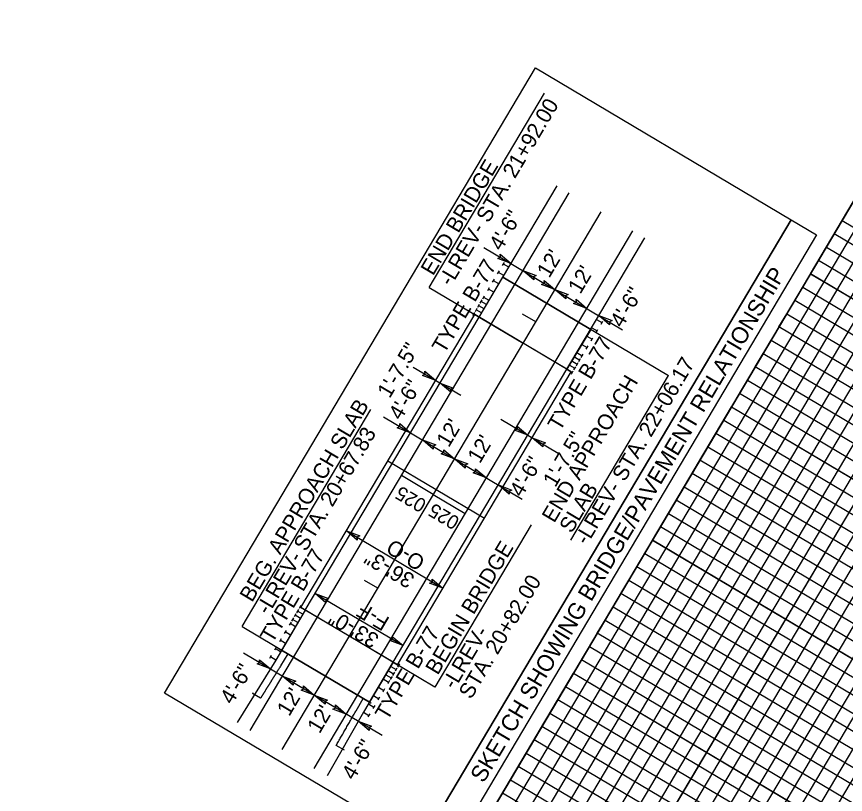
# Model space of a CAD drawing. Extents: x 2137081 to 2142019, y 404041 to 411238.
# Drawn here: x 2140819.3 to 2141087, y 409749.2 to 410000.3 of the extents above; entities that cross this region are included whole.
import ezdxf

# ---------------------------------------------------------------- set-up
doc = ezdxf.new("R2010")
doc.units = 0
for name, color, linetype in [('Prop Approach Slab', 7, 'Continuous'), ('Prop Approach Slab Hatching', 7, 'Continuous'), ('Prop Dimension', 7, 'Continuous'), ('Prop Dimension Text', 7, 'Continuous'), ('Prop EOT', 7, 'Continuous'), ('Prop Horizontal Alignment', 7, 'Continuous'), ('Prop Horizontal Alignment Tick Small', 7, 'Continuous'), ('Prop Roadway Bridge', 7, 'Continuous'), ('Prop SBG', 7, 'Continuous'), ('Prop Structure Anchor Unit CELL', 7, 'Continuous'), ('Prop Superelevation  Arrow CELL', 7, 'Continuous'), ('Prop Terminator CELL', 7, 'Continuous'), ('Sheet Clip Boundary CELL', 7, 'Continuous'), ('Sheet DOT Grid CELL', 7, 'Continuous'), ('Sheet Layout Profile Border Port 2', 7, 'Continuous'), ('Sheet Profile Grid Major CELL', 7, 'Continuous'), ('Sheet Profile Grid Middle CELL', 7, 'Continuous'), ('Sheet Profile Grid Minor CELL', 7, 'Continuous')]:
    doc.layers.add(name, color=color, linetype=linetype)

msp = doc.modelspace()

# ---------------------------------------------------------------- linework, layer by layer
at = {"layer": 'Prop Approach Slab'}
for p, q in [((2140968.66, 409903.27), (2140976.32, 409916.17)), ((2141004.7, 409899.32), (2140976.32, 409916.17)), ((2140912.52, 409808.67), (2140904.86, 409795.77)), ((2140933.24, 409778.93), (2140904.86, 409795.77))]:
    msp.add_line(p, q, dxfattribs=at)
at = {"layer": 'Prop Approach Slab Hatching'}
for points in [[(2140968.66, 409903.27), (2140976.32, 409916.17), (2141004.7, 409899.32), (2140997.04, 409886.42)], [(2140933.24, 409778.93), (2140940.9, 409791.83), (2140912.52, 409808.67), (2140904.86, 409795.77)]]:
    msp.add_lwpolyline(points, close=True, dxfattribs=at)
at = {"layer": 'Prop Dimension'}
for p, q in [((2140970.23, 409925.79), (2141015.01, 409899.21)), ((2140952.51, 409912.85), (2140982.85, 409894.84)), ((2140990.51, 409907.74), (2141029.85, 409884.39)), ((2140947.31, 409887.17), (2140962.72, 409878.03)), ((2140937.77, 409871.1), (2140982.55, 409844.52)), ((2140975.64, 409870.36), (2140994.15, 409859.38)), ((2140925.81, 409834.25), (2140956.98, 409815.75)), ((2140915.71, 409814.05), (2140944.09, 409797.21)), ((2140892.1, 409803.35), (2140919.05, 409787.35)), ((2140892.52, 409794.86), (2140937.3, 409768.28)), ((2140954.34, 409783.85), (2140934.08, 409795.87))]:
    msp.add_line(p, q, dxfattribs=at)
at = {"layer": 'Prop Dimension Text'}
for p, q in [((2140952.51, 409912.85), (2140989.73, 409975.56)), ((2140998.33, 409831.28), (2141029.85, 409884.39)), ((2140892.1, 409803.35), (2140933.67, 409873.4)), ((2140985.42, 409836.22), (2140954.34, 409783.85))]:
    msp.add_line(p, q, dxfattribs=at)
for points in [[(2141069.43, 409934.69), (2140949.64, 409732.86), (2140867.04, 409781.89), (2140986.83, 409983.72)], [(2140949.64, 409732.86), (2141069.43, 409934.69), (2141077.67, 409929.8), (2140957.88, 409727.97)]]:
    msp.add_lwpolyline(points, close=True, dxfattribs=at)
at = {"layer": 'Prop EOT'}
for p, q in [((2140978.23, 409919.39), (2140993.85, 409945.69)), ((2140894.69, 409769.82), (2140997.72, 409943.4)), ((2140915.33, 409757.57), (2141018.35, 409931.15)), ((2141006.61, 409902.55), (2141022.22, 409928.85)), ((2140902.95, 409792.55), (2140890.49, 409772.43)), ((2140931.33, 409775.71), (2140919.53, 409755.16))]:
    msp.add_line(p, q, dxfattribs=at)
at = {"layer": 'Prop Horizontal Alignment'}
msp.add_line((2140905.01, 409763.7), (2141008.03, 409937.27), dxfattribs=at)
at = {"layer": 'Prop Horizontal Alignment Tick Small'}
for p, q in [((2140986.94, 409901.72), (2140982.64, 409904.28)), ((2140935.89, 409815.73), (2140931.6, 409818.28))]:
    msp.add_line(p, q, dxfattribs=at)
at = {"layer": 'Prop Roadway Bridge'}
for p, q in [((2140911.12, 409809.5), (2140967.27, 409904.1)), ((2140998.44, 409885.59), (2140967.27, 409904.1)), ((2140912.52, 409808.67), (2140968.66, 409903.27)), ((2140940.9, 409791.83), (2140997.04, 409886.42)), ((2140942.29, 409791), (2140998.44, 409885.59)), ((2140970.37, 409838.3), (2140939.19, 409856.8)), ((2140942.29, 409791), (2140911.12, 409809.5))]:
    msp.add_line(p, q, dxfattribs=at)
at = {"layer": 'Prop SBG'}
for p, q in [((2140904.26, 409796.13), (2140904.86, 409795.77)), ((2140906.87, 409794.58), (2140904.53, 409790.65)), ((2140895.6, 409782.01), (2140895.47, 409781.78)), ((2140898.07, 409780.24), (2140895.47, 409781.78)), ((2140896.19, 409781.64), (2140896.06, 409781.43)), ((2140928.9, 409776.18), (2140931.24, 409780.12)), ((2140933.84, 409778.57), (2140933.24, 409778.93)), ((2140925.13, 409763.51), (2140922.5, 409765.02))]:
    msp.add_line(p, q, dxfattribs=at)
msp.add_open_spline([(2140904.5, 409790.61), (2140904.23, 409790.16), (2140903.95, 409789.71), (2140903.67, 409789.27), (2140903.53, 409789.04), (2140903.4, 409788.82), (2140903.26, 409788.6), (2140903.12, 409788.37), (2140902.98, 409788.15), (2140902.84, 409787.93), (2140902.7, 409787.7), (2140902.56, 409787.48), (2140902.42, 409787.26), (2140902.29, 409787.03), (2140902.15, 409786.81), (2140902.01, 409786.59), (2140901.87, 409786.36), (2140901.73, 409786.14), (2140901.59, 409785.92), (2140901.45, 409785.69), (2140901.32, 409785.47), (2140901.18, 409785.25), (2140901.04, 409785.02), (2140900.9, 409784.8), (2140900.76, 409784.58), (2140900.62, 409784.35), (2140900.48, 409784.13), (2140900.35, 409783.91), (2140900.21, 409783.69), (2140900.07, 409783.46), (2140899.93, 409783.24), (2140899.79, 409783.02), (2140899.65, 409782.79), (2140899.51, 409782.57), (2140899.37, 409782.35), (2140899.24, 409782.12), (2140899.1, 409781.9), (2140898.96, 409781.68), (2140898.82, 409781.45), (2140898.68, 409781.23), (2140898.54, 409781.01), (2140898.4, 409780.78), (2140898.27, 409780.56), (2140898.2, 409780.45), (2140898.13, 409780.34), (2140898.07, 409780.24)], degree=3, dxfattribs=at)
msp.add_spline([(2140922.5, 409765.02), (2140922.66, 409765.31), (2140923.05, 409765.98), (2140923.44, 409766.66), (2140923.83, 409767.34), (2140924.22, 409768.02), (2140924.61, 409768.69), (2140925, 409769.37), (2140925.38, 409770.05), (2140925.77, 409770.73), (2140926.16, 409771.41), (2140926.55, 409772.08), (2140926.94, 409772.76), (2140927.33, 409773.44), (2140927.72, 409774.12), (2140928.1, 409774.8), (2140928.88, 409776.15)], degree=3, dxfattribs=at)
at = {"layer": 'Prop Structure Anchor Unit CELL'}
for p, q in [((2140976.22, 409919.92), (2140976.81, 409920.9)), ((2140978.23, 409919.39), (2140976.51, 409920.41)), ((2140968.66, 409903.27), (2140978.23, 409919.39)), ((2140974.63, 409917.23), (2140975.21, 409918.22)), ((2140976.64, 409916.7), (2140974.92, 409917.72)), ((2140973.03, 409914.54), (2140973.62, 409915.53)), ((2140975.04, 409914.02), (2140973.32, 409915.04)), ((2140971.44, 409911.86), (2140972.02, 409912.84)), ((2140973.45, 409911.33), (2140971.73, 409912.35)), ((2140969.84, 409909.17), (2140970.43, 409910.15)), ((2140971.85, 409908.64), (2140970.13, 409909.66)), ((2140968.25, 409906.48), (2140968.83, 409907.47)), ((2140970.26, 409905.95), (2140968.54, 409906.97)), ((2140969.04, 409907.83), (2140969.63, 409908.81)), ((2140971.06, 409907.3), (2140969.34, 409908.32)), ((2140966.65, 409903.79), (2140967.24, 409904.78)), ((2140968.66, 409903.27), (2140966.94, 409904.29)), ((2140967.45, 409905.14), (2140968.03, 409906.12)), ((2140969.46, 409904.61), (2140967.74, 409905.63)), ((2140997.04, 409886.42), (2141006.61, 409902.55)), ((2141006.61, 409902.55), (2141008.33, 409901.53)), ((2141008.04, 409901.03), (2141008.62, 409902.02)), ((2141005.02, 409899.86), (2141006.74, 409898.84)), ((2141006.44, 409898.35), (2141007.03, 409899.33)), ((2141003.42, 409897.17), (2141005.14, 409896.15)), ((2141004.85, 409895.66), (2141005.43, 409896.64)), ((2141001.83, 409894.48), (2141003.55, 409893.46)), ((2141003.25, 409892.97), (2141003.84, 409893.96)), ((2140999.43, 409890.45), (2141001.15, 409889.43)), ((2141000.23, 409891.8), (2141001.95, 409890.78)), ((2141001.66, 409890.28), (2141002.24, 409891.27)), ((2140997.84, 409887.77), (2140999.56, 409886.75)), ((2140998.64, 409889.11), (2141000.36, 409888.09)), ((2141000.06, 409887.6), (2141000.65, 409888.58)), ((2141000.86, 409888.94), (2141001.45, 409889.93)), ((2140997.04, 409886.42), (2140998.76, 409885.4)), ((2140998.47, 409884.91), (2140999.05, 409885.89)), ((2140999.27, 409886.25), (2140999.85, 409887.24)), ((2140911.09, 409810.19), (2140910.51, 409809.2)), ((2140912.52, 409808.67), (2140902.95, 409792.55)), ((2140909.5, 409807.5), (2140908.91, 409806.51)), ((2140910.29, 409808.84), (2140909.71, 409807.86)), ((2140911.72, 409807.33), (2140910, 409808.35)), ((2140912.52, 409808.67), (2140910.8, 409809.69)), ((2140907.9, 409804.81), (2140907.32, 409803.83)), ((2140908.7, 409806.16), (2140908.11, 409805.17)), ((2140910.13, 409804.64), (2140908.41, 409805.66)), ((2140910.92, 409805.99), (2140909.2, 409807.01)), ((2140906.31, 409802.12), (2140905.72, 409801.14)), ((2140909.33, 409803.3), (2140907.61, 409804.32)), ((2140904.71, 409799.44), (2140904.13, 409798.45)), ((2140907.73, 409800.61), (2140906.01, 409801.63)), ((2140903.12, 409796.75), (2140902.53, 409795.77)), ((2140906.14, 409797.92), (2140904.42, 409798.94)), ((2140901.52, 409794.06), (2140900.94, 409793.08)), ((2140904.54, 409795.24), (2140902.82, 409796.26)), ((2140902.95, 409792.55), (2140901.23, 409793.57)), ((2140940.9, 409791.83), (2140931.33, 409775.71)), ((2140940.9, 409791.83), (2140942.62, 409790.81)), ((2140939.3, 409789.14), (2140941.02, 409788.12)), ((2140940.1, 409790.49), (2140941.82, 409789.47)), ((2140942.11, 409789.96), (2140941.53, 409788.97)), ((2140942.91, 409791.3), (2140942.32, 409790.32)), ((2140937.71, 409786.46), (2140939.43, 409785.43)), ((2140938.5, 409787.8), (2140940.22, 409786.78)), ((2140940.52, 409787.27), (2140939.93, 409786.29)), ((2140941.31, 409788.61), (2140940.73, 409787.63)), ((2140936.11, 409783.77), (2140937.83, 409782.75)), ((2140939.72, 409785.93), (2140939.13, 409784.94)), ((2140934.52, 409781.08), (2140936.24, 409780.06)), ((2140938.12, 409783.24), (2140937.54, 409782.25)), ((2140932.92, 409778.39), (2140934.64, 409777.37)), ((2140936.53, 409780.55), (2140935.94, 409779.57)), ((2140931.33, 409775.71), (2140933.05, 409774.69)), ((2140934.93, 409777.87), (2140934.35, 409776.88)), ((2140933.34, 409775.18), (2140932.75, 409774.19))]:
    msp.add_line(p, q, dxfattribs=at)
at = {"layer": 'Prop Superelevation  Arrow CELL'}
for q in [(2140943.54, 409852.13), (2140964.18, 409839.88)]:
    msp.add_line((2140953.86, 409846), q, dxfattribs=at)
at = {"layer": 'Prop Terminator CELL'}
for points in [[(2140975.48, 409923.57), (2140978.96, 409920.61), (2140974.66, 409922.23), (2140975.56, 409922.63)], [(2140986.3, 409915.35), (2140982.83, 409918.31), (2140987.13, 409916.69), (2140986.22, 409916.3)], [(2140989.67, 409915.15), (2140993.15, 409912.19), (2140988.85, 409913.81), (2140989.75, 409914.21)], [(2140996.62, 409909.23), (2140993.15, 409912.19), (2140997.45, 409910.57), (2140996.54, 409910.17)], [(2140999.99, 409909.03), (2141003.47, 409906.06), (2140999.17, 409907.69), (2141000.07, 409908.08)], [(2141010.81, 409900.8), (2141007.34, 409903.77), (2141011.64, 409902.15), (2141010.73, 409901.75)], [(2140951.17, 409885.79), (2140954.64, 409882.82), (2140950.34, 409884.45), (2140951.24, 409884.84)], [(2140959.51, 409879.03), (2140956.04, 409881.99), (2140960.34, 409880.37), (2140959.43, 409879.98)], [(2140943.03, 409868.89), (2140946.5, 409865.92), (2140942.2, 409867.55), (2140943.1, 409867.94)], [(2140980.94, 409868.11), (2140984.42, 409865.15), (2140980.12, 409866.77), (2140981.02, 409867.17)], [(2140953.84, 409860.66), (2140950.37, 409863.63), (2140954.67, 409862.01), (2140953.77, 409861.61)], [(2140989.29, 409861.36), (2140985.81, 409864.32), (2140990.11, 409862.7), (2140989.21, 409862.31)], [(2140957.21, 409860.47), (2140960.69, 409857.5), (2140956.39, 409859.12), (2140957.29, 409859.52)], [(2140964.16, 409854.54), (2140960.69, 409857.5), (2140964.99, 409855.88), (2140964.08, 409855.49)], [(2140967.53, 409854.34), (2140971.01, 409851.38), (2140966.71, 409853), (2140967.61, 409853.39)], [(2140978.35, 409846.12), (2140974.88, 409849.08), (2140979.18, 409847.46), (2140978.27, 409847.06)], [(2140929.28, 409831.29), (2140925.81, 409834.25), (2140930.11, 409832.63), (2140929.21, 409832.23)], [(2140953.51, 409818.71), (2140956.98, 409815.75), (2140952.68, 409817.37), (2140953.59, 409817.76)], [(2140919.18, 409811.09), (2140915.71, 409814.05), (2140920.01, 409812.43), (2140919.11, 409812.04)], [(2140940.61, 409800.17), (2140944.09, 409797.21), (2140939.79, 409798.83), (2140940.69, 409799.22)], [(2140897.77, 409792.64), (2140901.24, 409789.68), (2140896.94, 409791.3), (2140897.85, 409791.69)], [(2140908.59, 409784.42), (2140905.11, 409787.38), (2140909.41, 409785.76), (2140908.51, 409785.36)], [(2140911.96, 409784.22), (2140915.43, 409781.25), (2140911.13, 409782.88), (2140912.04, 409783.27)], [(2140918.91, 409778.29), (2140915.43, 409781.25), (2140919.73, 409779.63), (2140918.83, 409779.24)], [(2140922.28, 409778.09), (2140925.75, 409775.13), (2140921.45, 409776.75), (2140922.35, 409777.15)], [(2140933.1, 409769.87), (2140929.62, 409772.83), (2140933.92, 409771.21), (2140933.02, 409770.82)]]:
    msp.add_lwpolyline(points, close=True, dxfattribs=at)
at = {"layer": 'Sheet Clip Boundary CELL'}
msp.add_lwpolyline([(2140795, 409444.32), (2141473.2, 410586.96), (2141453.94, 410598.39), (2141513.05, 410697.97), (2141213, 410886.12), (2141134.78, 410754.33), (2141040.49, 410810.3), (2140938.2, 410637.97), (2140883.25, 410670.58), (2140322.04, 409725.04)], close=True, dxfattribs=at)
at = {"layer": 'Sheet DOT Grid CELL'}
for p, q in [((2140795, 409444.32), (2141560.61, 410734.22)), ((2140838, 409418.8), (2141603.6, 410708.7)), ((2141075.72, 409917.29), (2141484.19, 409674.84)), ((2141050.2, 409874.29), (2141458.67, 409631.85)), ((2141024.68, 409831.29), (2141433.15, 409588.85)), ((2140999.16, 409788.3), (2141407.63, 409545.85))]:
    msp.add_line(p, q, dxfattribs=at)
at = {"layer": 'Sheet Layout Profile Border Port 2'}
msp.add_lwpolyline([(2140820.52, 409487.32), (2141535.09, 410691.23), (2141943.55, 410448.78), (2141228.99, 409244.88)], close=True, dxfattribs=at)
at = {"layer": 'Sheet Profile Grid Major CELL'}
for points in [[(2140795, 409444.32), (2141560.61, 410734.22)], [(2141603.6, 410708.7), (2140838, 409418.8), (2140880.99, 409393.28), (2141646.6, 410683.18)], [(2141484.19, 409674.84), (2141075.72, 409917.29), (2141101.24, 409960.28), (2141509.71, 409717.84)], [(2141433.15, 409588.85), (2141024.68, 409831.29), (2141050.2, 409874.29), (2141458.67, 409631.85)], [(2141382.11, 409502.86), (2140973.64, 409745.3), (2140999.16, 409788.3), (2141407.63, 409545.85)]]:
    msp.add_lwpolyline(points, dxfattribs=at)
at = {"layer": 'Sheet Profile Grid Middle CELL'}
for p, q in [((2140816.5, 409431.56), (2141582.1, 410721.46)), ((2141625.1, 410695.94), (2140859.49, 409406.04))]:
    msp.add_line(p, q, dxfattribs=at)
for points in [[(2141445.91, 409610.35), (2141037.44, 409852.79), (2141062.96, 409895.79), (2141471.43, 409653.35)], [(2141394.87, 409524.35), (2140986.4, 409766.8), (2141011.92, 409809.79), (2141420.39, 409567.35)]]:
    msp.add_lwpolyline(points, dxfattribs=at)
at = {"layer": 'Sheet Profile Grid Minor CELL'}
for points in [[(2141539.38, 410688.67), (2140824.82, 409484.77)], [(2141547.98, 410683.57), (2140833.42, 409479.66), (2140829.12, 409482.21), (2141543.68, 410686.12)], [(2141560.88, 410675.91), (2140846.32, 409472.01), (2140842.02, 409474.56), (2140837.72, 409477.11), (2141552.28, 410681.02)], [(2141569.48, 410670.81), (2140854.92, 409466.9), (2140850.62, 409469.45), (2141565.18, 410673.36)], [(2141582.38, 410663.15), (2140867.82, 409459.25), (2140863.52, 409461.8), (2140859.22, 409464.35), (2141573.78, 410668.26)], [(2141590.98, 410658.05), (2140876.42, 409454.14), (2140872.12, 409456.69), (2141586.68, 410660.6)], [(2141603.88, 410650.39), (2140889.31, 409446.49), (2140885.01, 409449.04), (2140880.72, 409451.59), (2141595.28, 410655.5)], [(2141612.48, 410645.29), (2140897.91, 409441.38), (2140893.61, 409443.93), (2141608.18, 410647.84)], [(2140910.81, 409433.73), (2140906.51, 409436.28), (2140902.21, 409438.83), (2141616.78, 410642.74)], [(2141491.85, 409687.74), (2141083.38, 409930.18), (2141085.93, 409934.48), (2141494.4, 409692.04)], [(2141486.74, 409679.14), (2141078.27, 409921.58), (2141080.83, 409925.88), (2141489.29, 409683.44)], [(2141479.09, 409666.24), (2141070.62, 409908.69), (2141073.17, 409912.99), (2141481.64, 409670.54)], [(2141473.98, 409657.64), (2141065.51, 409900.09), (2141068.07, 409904.39), (2141476.53, 409661.94)], [(2141466.33, 409644.75), (2141057.86, 409887.19), (2141060.41, 409891.49), (2141468.88, 409649.05)], [(2141461.22, 409636.15), (2141052.75, 409878.59), (2141055.31, 409882.89), (2141463.77, 409640.45)], [(2141453.57, 409623.25), (2141045.1, 409865.69), (2141047.65, 409869.99), (2141456.12, 409627.55)], [(2141448.46, 409614.65), (2141039.99, 409857.09), (2141042.55, 409861.39), (2141451.01, 409618.95)], [(2141440.81, 409601.75), (2141032.34, 409844.19), (2141034.89, 409848.49), (2141443.36, 409606.05)], [(2141435.7, 409593.15), (2141027.23, 409835.59), (2141029.79, 409839.89), (2141438.25, 409597.45)], [(2141428.05, 409580.25), (2141019.58, 409822.69), (2141022.13, 409826.99), (2141430.6, 409584.55)], [(2141422.94, 409571.65), (2141014.47, 409814.09), (2141017.03, 409818.39), (2141425.49, 409575.95)], [(2141415.29, 409558.75), (2141006.82, 409801.19), (2141009.37, 409805.49), (2141417.84, 409563.05)], [(2141410.18, 409550.15), (2141001.71, 409792.59), (2141004.27, 409796.89), (2141412.73, 409554.45)], [(2141402.53, 409537.25), (2140994.06, 409779.7), (2140996.61, 409784), (2141405.08, 409541.55)], [(2141397.42, 409528.65), (2140988.95, 409771.1), (2140991.51, 409775.4), (2141399.97, 409532.95)], [(2141389.77, 409515.76), (2140981.3, 409758.2), (2140983.85, 409762.5), (2141392.32, 409520.06)], [(2141384.66, 409507.16), (2140976.19, 409749.6), (2140978.74, 409753.9), (2141387.21, 409511.46)]]:
    msp.add_lwpolyline(points, dxfattribs=at)

# ---------------------------------------------------------------- texts
at = {"layer": 'Prop Dimension Text'}
for s, height, rotation, p in [('-LREV- STA. 21+92.00', 5, 59.3093, (2140959.56, 409912.94)), ('END BRIDGE', 5, 59.3093, (2140953.78, 409916.39)), ('4\'-6"', 5, 59.3093, (2140975.83, 409924.36)), ("12'", 5, 59.3093, (2140991.3, 409915.63)), ('TYPE B-77', 5, 59.3093, (2140957.42, 409891.23)), ("12'", 5, 59.3093, (2141001.34, 409910.44)), ('SKETCH SHOWING BRIDGE/PAVEMENT RELATIONSHIP', 5.36, 59.3093, (2140970.1, 409752.59)), ('4\'-6"', 5, 59.3093, (2141014.89, 409899.54)), ('TYPE B-77', 5, 59.3093, (2140994.8, 409866.18)), ('1\'-7.5"', 5, 59.3093, (2140939.76, 409876.81)), ('-LREV- STA. 22+06.17', 5, 59.3093, (2141003.49, 409829.41)), ('4\'-6"', 5, 59.3093, (2140943.37, 409869.67)), ('END APPROACH', 5, 59.3093, (2140992.91, 409836.57)), ('BEG. APPROACH SLAB', 5, 59.3093, (2140895.32, 409810.96)), ("12'", 5, 59.3093, (2140958.84, 409860.94)), ('-LREV- STA. 20+67.83', 5, 59.3093, (2140900.59, 409806.89)), ('1\'-7.5"', 5, 59.3093, (2140993.26, 409848.05)), ("12'", 5, 59.3093, (2140968.89, 409855.75)), ('4\'-6"', 5, 59.3093, (2140982.43, 409844.86)), ('SLAB', 5, 59.3093, (2140998.54, 409833.22)), ('O-O', 5, 149.3093, (2140951.59, 409825.37)), ('BEGIN BRIDGE', 5, 59.3093, (2140955.3, 409787.47)), ('TYPE B-77', 5, 59.3093, (2140901.93, 409797.73)), ('36\'-3"', 5, 149.3093, (2140948.24, 409819.73)), ('STA. 20+82.00', 5, 59.3093, (2140966.06, 409779.62)), ('F-F', 5, 149.3093, (2140940.09, 409806)), ('33\'-0"', 5, 149.3093, (2140936.74, 409800.36)), ('TYPE B-77', 5, 59.3093, (2140939.04, 409772.77)), ('-LREV- ', 5, 59.3093, (2140960.69, 409782.81)), ('4\'-6"', 5, 59.3093, (2140888.92, 409777.93)), ("12'", 5, 59.3093, (2140907.31, 409774.12)), ("12'", 5, 59.3093, (2140917.13, 409768.56)), ('4\'-6"', 5, 59.3093, (2140928.2, 409753.49))]:
    msp.add_text(s, height=height, rotation=rotation, dxfattribs=at).set_placement(p)
at = {"layer": 'Prop Superelevation  Arrow CELL'}
for p in [(2140952.01, 409843.82), (2140962.69, 409838.26)]:
    msp.add_text('025', height=4.5, rotation=149.3093, dxfattribs=at).set_placement(p)

doc.saveas('drawing.dxf')
